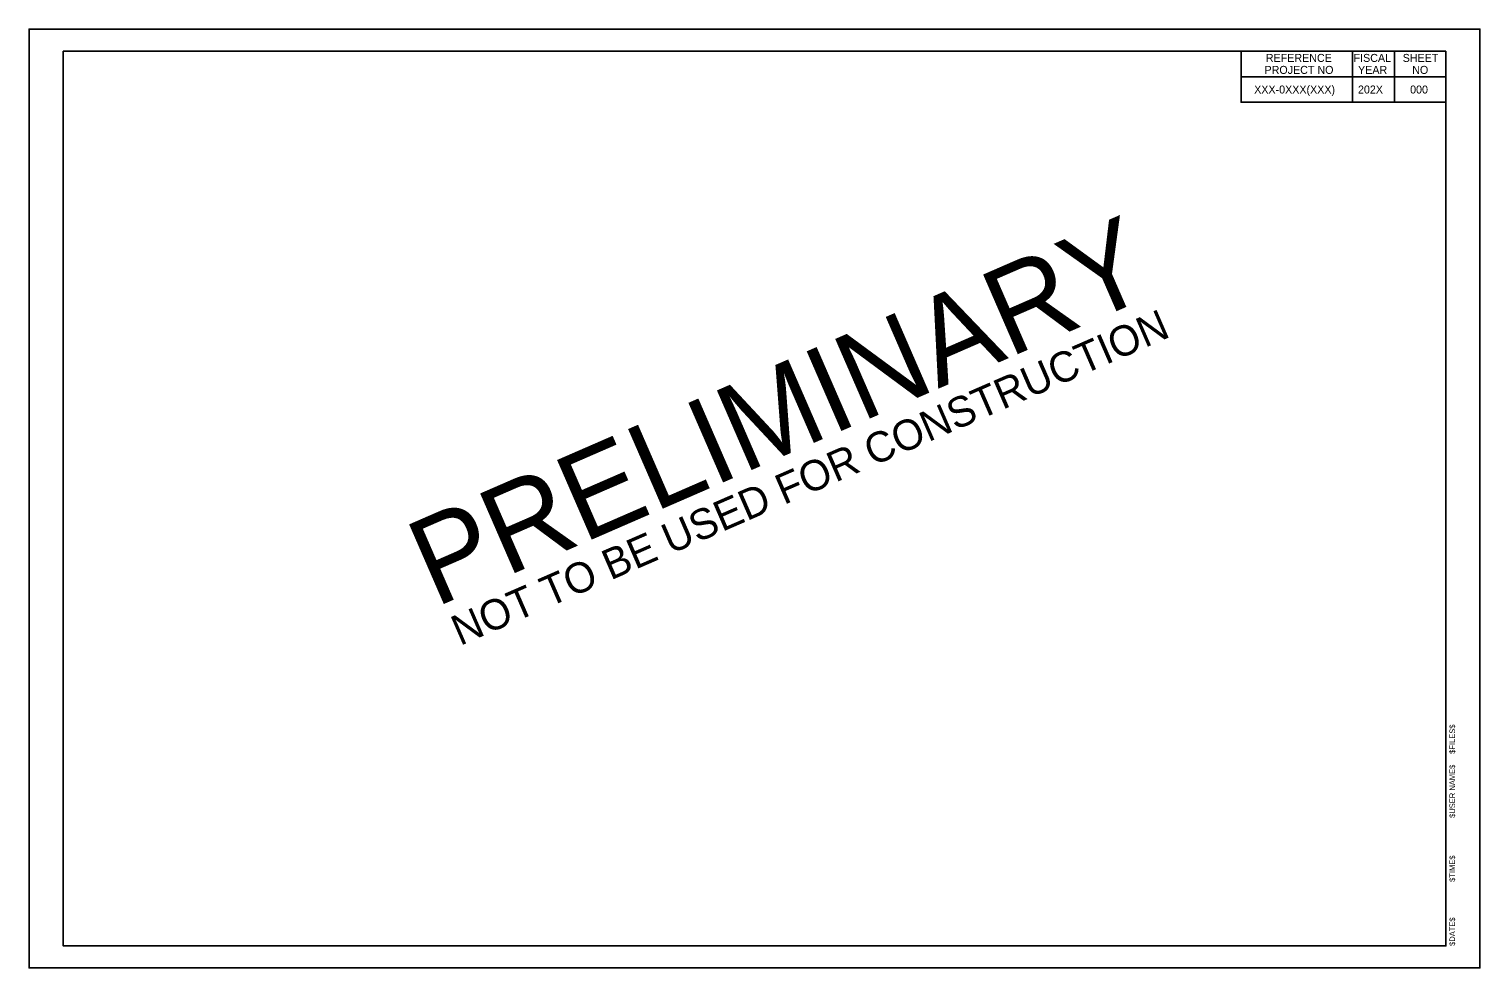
# Model space of a CAD drawing. Extents: x 0 to 2.83, y 0 to 1.83.
import ezdxf

# ---------------------------------------------------------------- set-up
doc = ezdxf.new("R2010")
doc.units = 0
for name, color, linetype in [('ANNO-SHT', 7, 'Continuous'), ('PRELIMINARY', 7, 'Continuous'), ('SHT-BDR', 7, 'Continuous'), ('SHT-FENCE', 7, 'Continuous')]:
    doc.layers.add(name, color=color, linetype=linetype)

msp = doc.modelspace()

# ---------------------------------------------------------------- linework, layer by layer
at = {"layer": 'SHT-BDR'}
for p, q in [((2.3667, 1.7902), (2.7667, 1.7902)), ((2.5842, 1.6902), (2.5842, 1.7902)), ((2.6667, 1.6902), (2.6667, 1.7902)), ((2.7667, 1.7902), (2.7667, 1.6902)), ((2.3667, 1.7402), (2.7667, 1.7402)), ((2.4767, 1.7152), (2.4767, 1.7152)), ((2.6267, 1.7152), (2.6267, 1.7152)), ((2.7167, 1.7152), (2.7167, 1.7152))]:
    msp.add_line(p, q, dxfattribs=at)
for points in [[(0, 0), (2.8333, 0), (2.8333, 1.8333), (0, 1.8333)], [(0.0667, 1.7902), (0.0667, 0.0431), (2.7667, 0.0431), (2.7667, 1.6902), (2.3667, 1.6902), (2.3667, 1.7902)]]:
    msp.add_lwpolyline(points, close=True, dxfattribs=at)
at = {"layer": 'SHT-FENCE'}
msp.add_lwpolyline([(0, 1.8333), (2.8333, 1.8333), (2.8333, 0), (0, 0)], close=True, dxfattribs=at)

# ---------------------------------------------------------------- texts
at = {"layer": 'ANNO-SHT'}
for s, height, p in [('PROJECT NO', 0.01562, (2.4126, 1.7457)), ('REFERENCE', 0.01562, (2.4152, 1.7691)), ('FISCAL', 0.01562, (2.5865, 1.7691)), ('YEAR', 0.01562, (2.5953, 1.7457)), ('SHEET', 0.01562, (2.6824, 1.7691)), ('NO', 0.01562, (2.701, 1.7457)), ('XXX-0XXX(XXX)', 0.015625, (2.3924, 1.7074)), ('202X', 0.01562, (2.5951, 1.7074)), ('000', 0.01562, (2.6969, 1.7074))]:
    msp.add_text(s, height=height, dxfattribs=at).set_placement(p)
for s, p in [('$FILES$', (2.7847, 0.4181)), ('$USER NAME$', (2.7847, 0.2931)), ('$TIME$', (2.7847, 0.1681)), ('$DATE$', (2.7847, 0.0431))]:
    msp.add_text(s, height=0.011, rotation=90, dxfattribs=at).set_placement(p)
at = {"layer": 'PRELIMINARY'}
for s, height, p in [('PRELIMINARY', 0.169591, (0.7929, 0.7032)), ('NOT TO BE USED FOR CONSTRUCTION', 0.059132, (0.8416, 0.6285))]:
    msp.add_text(s, height=height, rotation=23.5194, dxfattribs=at).set_placement(p)

doc.saveas('drawing.dxf')
